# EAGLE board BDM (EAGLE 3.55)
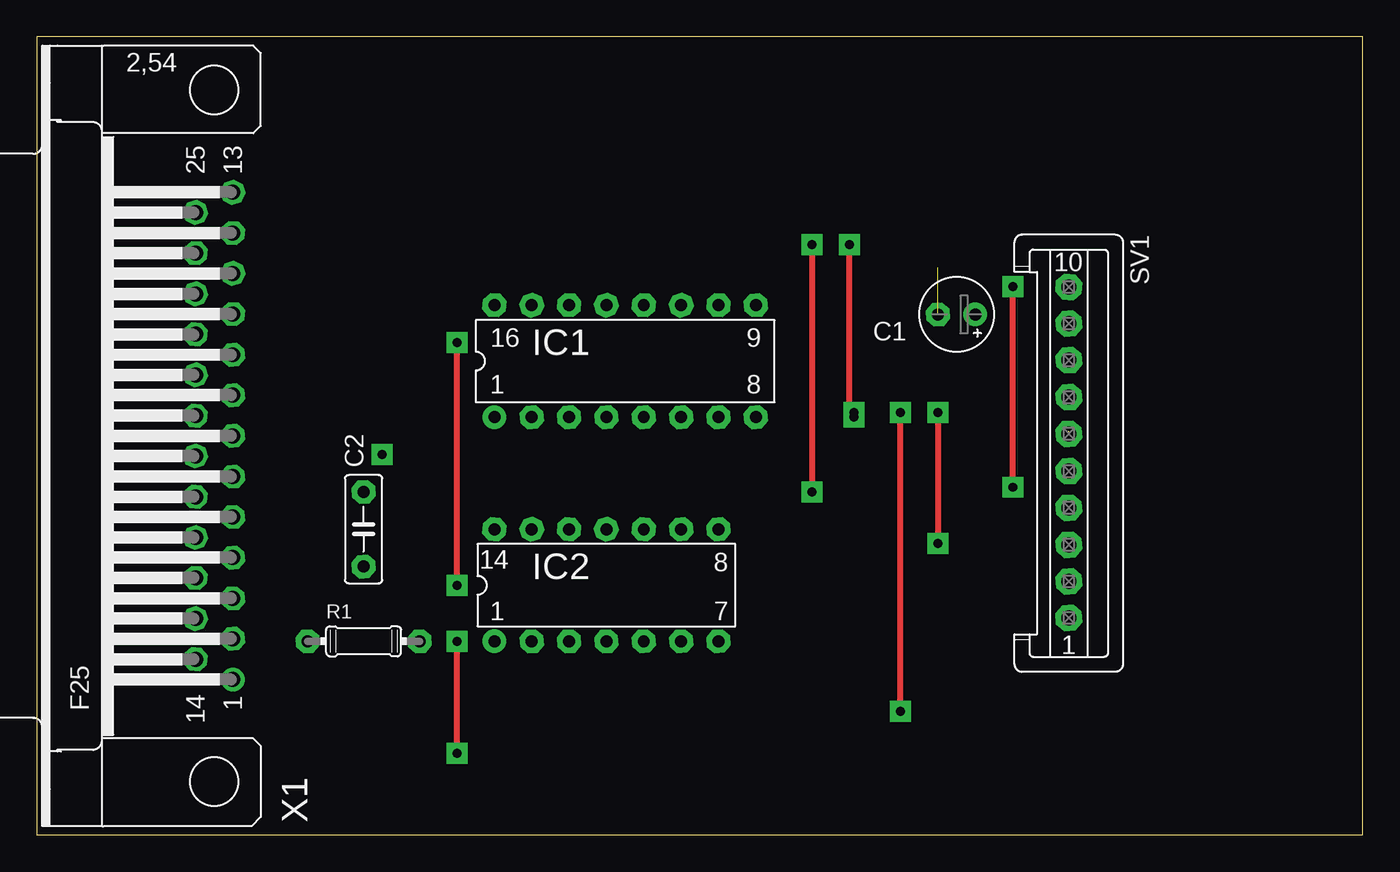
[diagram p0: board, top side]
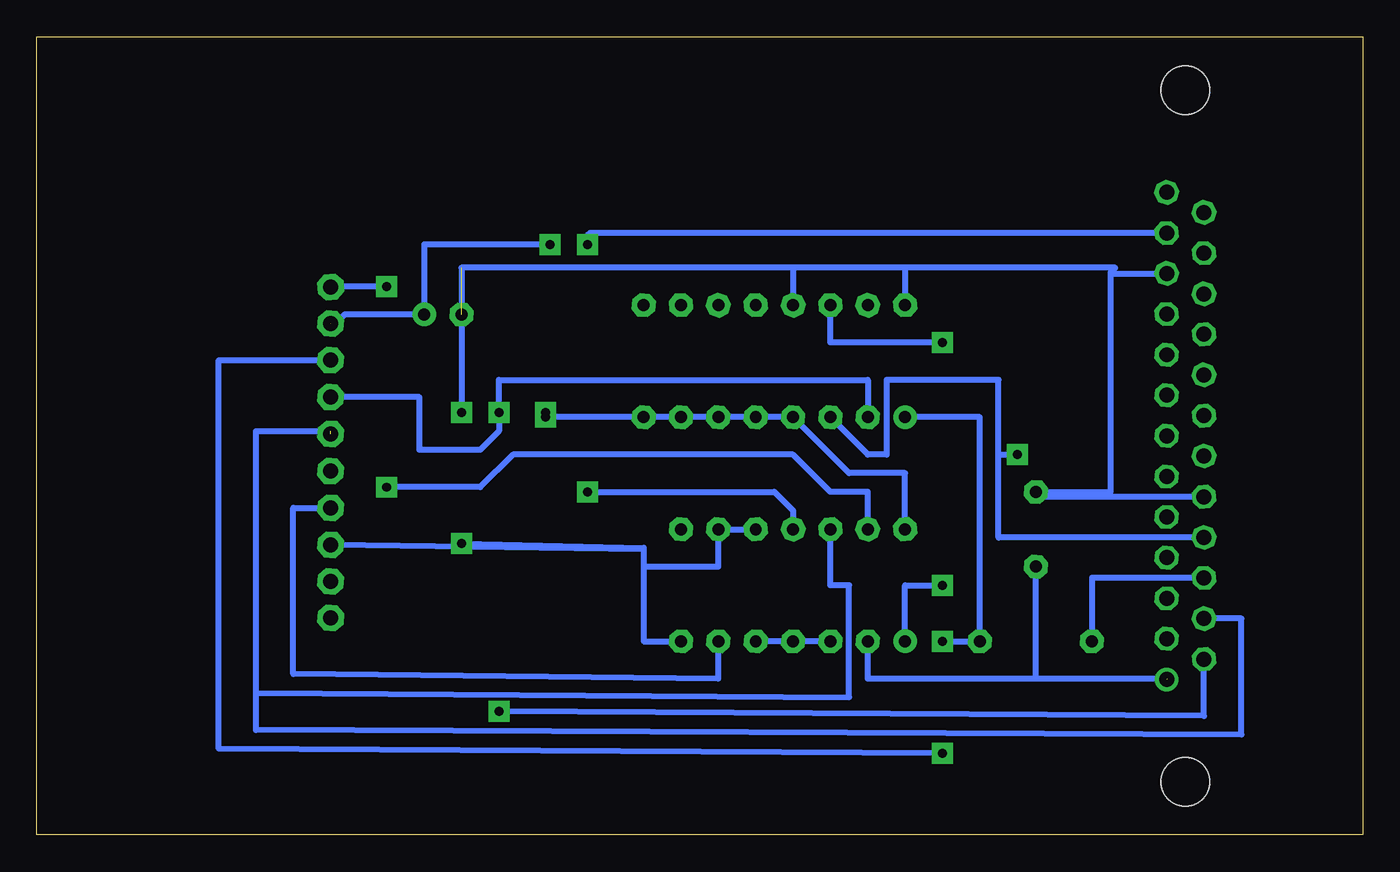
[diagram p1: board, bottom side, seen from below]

Size 90.15 x 54.28 mm. Coordinates in mm from the lower left corner, seen from the top.
Outline: 0,0 90.15,0 90.15,54.28 0,54.28 0,0
Copper layers used: Top, Bottom

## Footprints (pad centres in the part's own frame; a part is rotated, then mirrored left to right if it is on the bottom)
,5-5 = drill 0.813 pad 1.6 octagon:  1.27,0 | drill 0.813 pad 1.6 round:  -1.27,0
B2,5 = drill 0.813 pad 1.6 octagon:  -2.54,0;  2.54,0
L16 = drill 0.813 pad 1.6 round:  -8.89,-3.81 | drill 0.813 pad 1.6 octagon:  -6.35,-3.81;  -3.81,-3.81;  -1.27,-3.81;  1.27,-3.81;  3.81,-3.81;  6.35,-3.81;  8.89,-3.81;  8.89,3.81;  6.35,3.81;  3.81,3.81;  1.27,3.81;  -1.27,3.81;  -3.81,3.81;  -6.35,3.81;  -8.89,3.81
L14 = drill 0.813 pad 1.6 round:  -7.62,-3.81 | drill 0.813 pad 1.6 octagon:  -5.08,-3.81;  -2.54,-3.81;  0,-3.81;  2.54,-3.81;  5.08,-3.81;  7.62,-3.81;  7.62,3.81;  5.08,3.81;  2.54,3.81;  0,3.81;  -2.54,3.81;  -5.08,3.81;  -7.62,3.81
04/7 = drill 0.813 pad 1.6 octagon:  -3.81,0;  3.81,0
0P = drill 1.016 pad 1.778 octagon:  -17.526,0;  -15.011,0;  -4.978,0;  -12.522,0;  -9.982,0;  -7.493,0;  -2.489,0;  0,0;  -20.015,0;  -22.504,0
5H = drill 1.016 pad 1.6 round:  -16.561,-1.27 | drill 1.016 pad 1.6 octagon:  -13.792,-1.27;  -11.049,-1.27;  -8.28,-1.27;  -5.512,-1.27;  -2.769,-1.27;  0,-1.27;  2.769,-1.27;  5.512,-1.27;  8.28,-1.27;  11.049,-1.27;  13.792,-1.27;  16.561,-1.27;  -15.189,1.27;  -12.421,1.27;  -9.652,1.27;  -6.909,1.27;  -4.14,1.27;  -1.372,1.27;  1.372,1.27;  4.14,1.27;  6.909,1.27;  9.652,1.27;  12.421,1.27;  15.189,1.27 | hole 3.302: -23.52,0; 23.52,0

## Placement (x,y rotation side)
C1  E2,5-5  [,5-5]  62.54,35.39 180 top
C2  C5B2,5  [B2,5]  22.22,20.79 90 top
IC1  7476  [L16]  40,32.22 0 top
IC2  DIL14  [L14]  38.73,16.98 0 top
R1  0204/7  [04/7]  22.22,13.17 0 top
SV1  S10P  [0P]  70.16,14.76 270 top
X1  F25H  [5H]  12.06,27.14 90 top

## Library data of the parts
C1 = polcap
C2 = cap
IC1 = 74xx
IC2 = dil
R1 = r
SV1 = con-mt
X1 = subd

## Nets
+5V: C1. IC1. IC2. SV1.
GND: C1. C2. IC1. IC2. SV1. X1.
N$1: R1. X1.
N$2: IC1. R1. SV1.
N$3: IC1. X1.
N$4: IC1. SV1. X1.
N$5: IC1. IC2.
N$7: IC2.
N$9: IC2. SV1.
N$10: IC2. X1.
N$11: IC2. SV1. X1.
N$12: C2. IC2. X1.
N$13: IC2. SV1.

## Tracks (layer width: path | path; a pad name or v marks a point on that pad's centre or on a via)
+5V  (via drill 0.61 pad 1.42)  (1 unrouted)
  Top 0.406: v55.56,28.73 55.56,28.41 55.24,28.73 v55.24,40.16
  Bottom 0.406: 43.81,28.41 41.27,28.41 38.73,28.41 34.92,24.6 31.11,24.6 IC2. | 43.81,28.41 46.35,28.41 | 46.35,28.41 48.89,28.41 | 46.35,28.41 48.89,28.41 | 43.81,28.41 46.35,28.41 | 43.81,28.41 46.35,28.41 | 70.16,34.76 69.84,34.76 69.21,35.39 C1. 63.81,40.16 v55.24,40.16 | 48.89,28.41 55.24,28.41 v55.56,28.73
GND  (via drill 0.61 pad 1.42)  (1 unrouted)
  Top 0.406: v61.27,28.73 v61.27,19.84
  Bottom 0.406: 10.79,23 22.22,23 C2. 17.14,23.33 17.14,38.19 | 48.89,19.42 70.16,19.74 | 43.81,20.79 41.27,20.79 43.81,20.79 | 17.14,38.19 13.33,38.19 | 38.73,38.57 61.27,38.57 v61.27,28.73 | v61.27,19.84 48.89,19.52 48.89,19.42 | 31.11,38.57 IC1. | 31.11,38.57 38.73,38.57 | 38.73,38.57 38.73,36.03 | 43.81,20.79 43.81,18.25 48.89,18.25 48.89,19.42 | 48.89,19.42 48.89,13.17 46.35,13.17 | 17.14,38.19 17.14,38.25 16.82,38.57 31.11,38.57
N$1
  Bottom 0.406: 10.79,17.49 18.41,17.49 18.41,13.17
N$2  (via drill 0.61 pad 1.42)
  Top 0.406: v28.57,5.55 v28.57,13.17
  Bottom 0.406: 31.11,28.41 26.03,28.41 R1. v28.57,13.17 | 70.16,32.28 77.78,32.28 77.78,5.87 v28.57,5.55
N$3  (via drill 0.61 pad 1.42)
  Bottom 0.406: 10.79,20.23 24.76,20.23 24.76,25.87 | 24.76,25.87 v23.49,25.87 | 24.76,25.87 24.76,30.95 32.38,30.95 32.38,25.87 33.65,25.87 36.19,28.41
N$4  (via drill 0.61 pad 1.42)
  Top 0.406: v58.73,8.41 v58.73,28.73
  Bottom 0.406: 70.16,29.77 64.13,29.77 64.13,26.19 60,26.19 58.73,27.46 v58.73,28.73 58.73,30.95 33.65,30.95 33.65,28.41 | 10.79,11.95 10.79,8.09 v58.73,8.41
N$5  (via drill 0.61 pad 1.42)
  Top 0.406: v28.57,16.98 v28.57,33.49
  Bottom 0.406: 36.19,36.03 36.19,33.49 v28.57,33.49 | 31.11,13.17 31.11,16.98 v28.57,16.98
N$6  (via drill 0.61 pad 1.42)
  other vias: 52.7,40.16
N$7
  Bottom 0.406: 41.27,13.17 38.73,13.17 36.19,13.17
N$8  (via drill 0.61 pad 1.42)
  other vias: 66.35,37.3
N$9
  Bottom 0.406: 70.16,22.25 72.7,22.25 72.7,10.95 43.81,10.63 43.81,13.17
N$10  (via drill 0.61 pad 1.42)
  Top 0.406: v52.7,40.16 v52.7,23.33
  Bottom 0.406: 38.73,20.79 38.73,22.06 40,23.33 v52.7,23.33 | 13.33,40.93 52.52,40.93 52.7,40.79 v52.7,40.16
N$11  (1 unrouted)
  Bottom 0.406: 10.79,14.72 8.25,14.72 8.25,6.82 75.24,7.14 75.24,9.68 | 75.24,9.68 75.24,27.46 70.16,27.46 | 36.19,20.79 36.19,16.98 34.92,16.98 34.92,9.36 75.24,9.68
N$12  (1 unrouted)
  Bottom 0.406: 22.22,10.63 22.22,18.25 | 13.33,10.63 22.22,10.63 | 22.22,10.63 33.65,10.63 33.65,13.17
N$13  (via drill 0.61 pad 1.42)
  Top 0.406: v66.35,23.65 v66.35,37.3
  Bottom 0.406: 33.65,20.79 33.65,23.33 36.19,23.33 38.73,25.87 57.78,25.87 60,23.65 v66.35,23.65 | SV1. 70.16,37.3 v66.35,37.3
N$14  (via drill 0.61 pad 1.42)
  other vias: 66.35,23.65
N$15  (via drill 0.61 pad 1.42)
  other vias: 28.57,13.17
N$16  (via drill 0.61 pad 1.42)
  other vias: 28.57,5.55
N$17  (via drill 0.61 pad 1.42)
  other vias: 61.27,19.84
N$18  (via drill 0.61 pad 1.42)
  other vias: 28.57,33.49
N$19  (via drill 0.61 pad 1.42)
  other vias: 28.57,16.98
N$20  (via drill 0.61 pad 1.42)
  other vias: 55.24,40.16
N$21  (via drill 0.61 pad 1.42)
  other vias: 23.49,25.87
N$22  (via drill 0.61 pad 1.42)
  other vias: 55.56,28.41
